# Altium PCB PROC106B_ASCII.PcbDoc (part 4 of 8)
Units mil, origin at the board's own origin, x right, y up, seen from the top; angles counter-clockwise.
Board outline 4498.18 x 1060.53 mil, 8 copper layers (Top Layer, GND1, Sig1, PWR1, PWR2, Sig2, GND2, Bottom Layer), stack 69.602 mil thick; 439 components, 327 nets, 1548 pads, 843 vias.
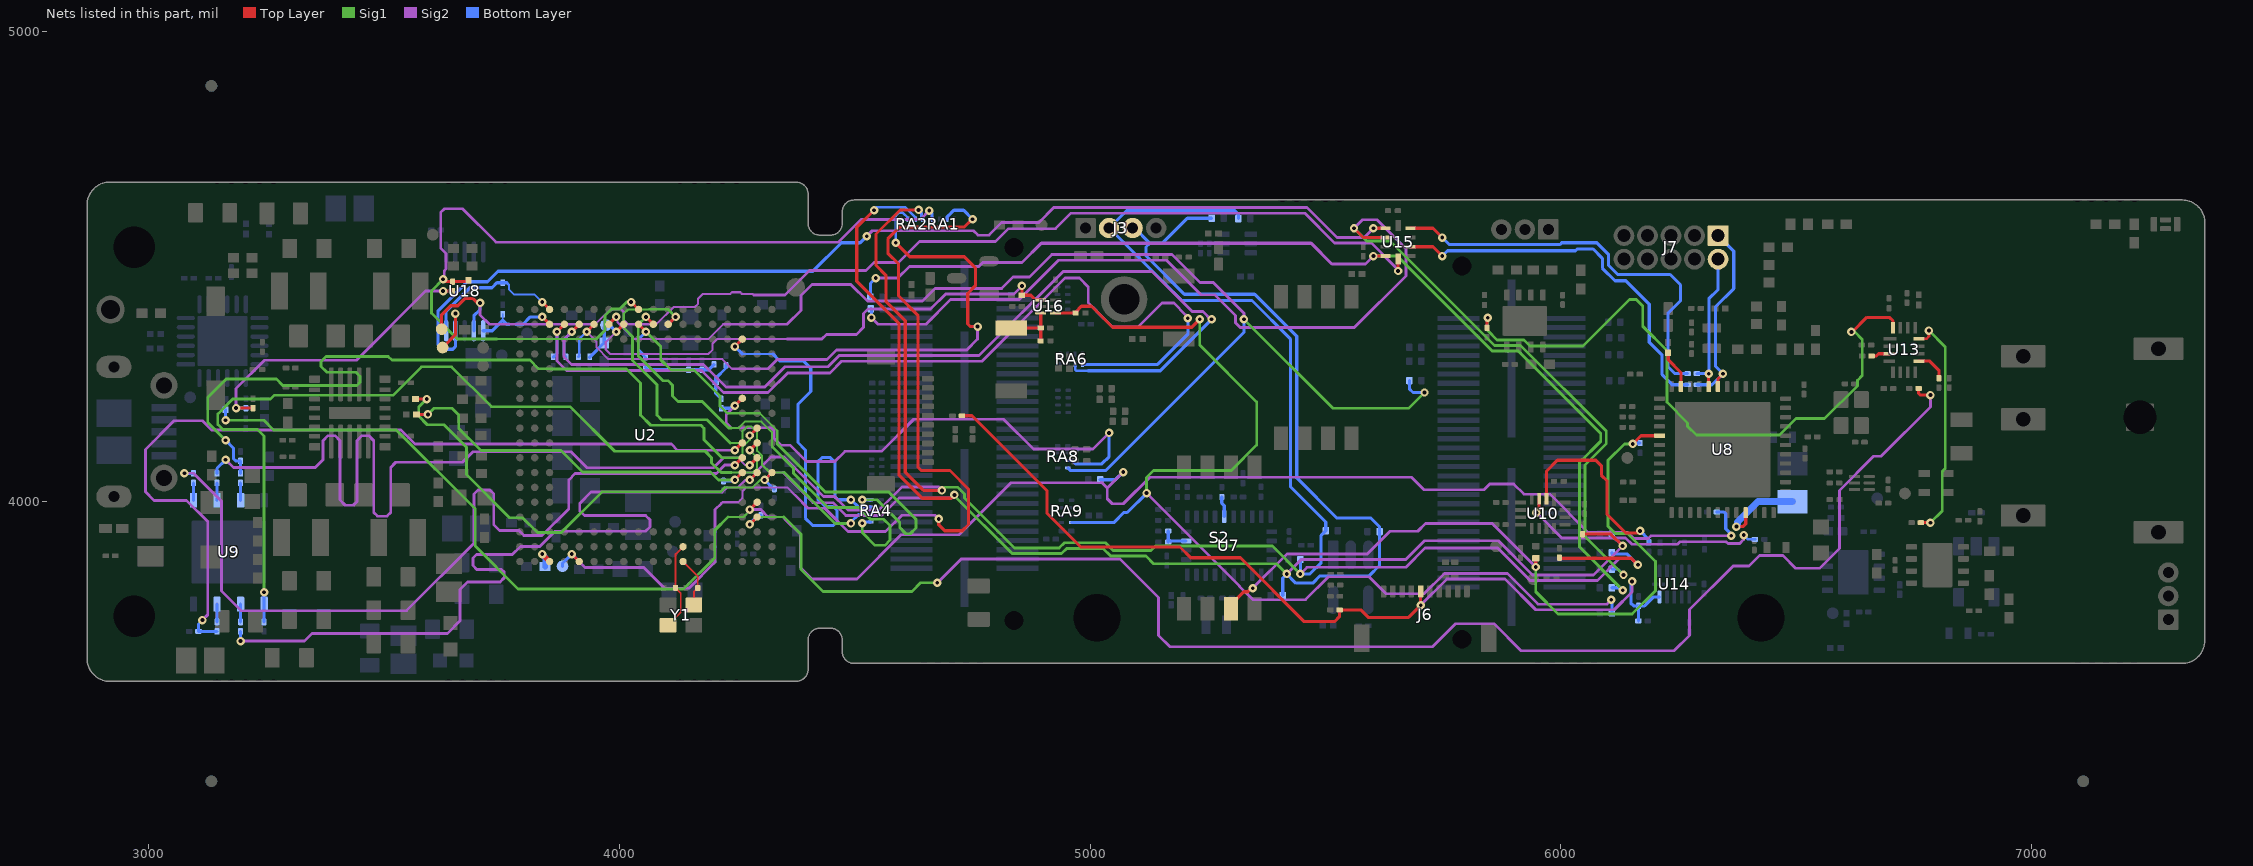
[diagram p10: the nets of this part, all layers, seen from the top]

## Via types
v1: diameter 18, hole 8, Top Layer to Bottom Layer, tented both sides, 804 vias
v2: diameter 19.68, hole 7.87, Top Layer to Bottom Layer, tented both sides, 34 vias
v3: diameter 20, hole 10, Top Layer to Bottom Layer, tented both sides, 3 vias
v4: diameter 18, hole 8, Top Layer to Bottom Layer, 1 vias
v5: diameter 17, hole 7.87, Top Layer to Bottom Layer, 1 vias

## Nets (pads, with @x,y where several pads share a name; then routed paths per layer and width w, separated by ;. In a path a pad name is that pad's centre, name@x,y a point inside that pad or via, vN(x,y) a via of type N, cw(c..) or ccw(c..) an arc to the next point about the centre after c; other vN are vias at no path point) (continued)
AR_MSS_LOGGER: R58.1 R61.1 R131.1 U2.E2 | length 4027.5
  Top Layer w6.7: v1(4276.95,3983.65) U2.E2@4292.7,3999.4
  Sig1 w4.5: 4230.89,3967.9 4263.85,3967.9 v1@4276.95,3981.01
  Sig1 w5.95: v1(3163.55,4173.41) 3244.94,4173.41 3265.5,4152.85 3526.01,4152.85 3694.1,3984.76 3694.1,3905.76 3784.97,3814.9 4136.48,3814.9 4202.76,3881.17 4202.76,3939.76 4230.89,3967.9 ; v1@4276.95,3981.01 v1(4276.95,3983.65)
  Sig2 w4.5: 4332.4,3967.9 4347.49,3967.9 4351.37,3964.02
  Sig2 w5.95: v1(4276.95,3983.65) 4300.25,3983.65 4316,3967.9 4332.4,3967.9 ; 4351.37,3964.02 4384.8,3930.59 4384.8,3860.7 4409.3,3836.2 4504.48,3836.2 4598.64,3930.36 4721.32,3930.36 4831.75,4040.79 5024.98,4040.79 5036.27,4029.5 ; v1(5070.29,4063.51) 5036.27,4029.5 ; v1(6361.81,3928) 6191.21,3928 6185.35,3922.14 6155.37,3922.14 6142.32,3935.19 6057.76,3935.19 5976.45,4016.5 5921.24,4016.5 5899.64,4038.09 5848.9,4038.09 5836.7,4025.89 5709.49,4025.89 5682.87,4052.51 5126.86,4052.51 5070.48,3996.13 5046.92,3996.13 5036.27,4006.77 5036.27,4029.5
  Bottom Layer w6.7: v1(3163.55,4173.41) R61.1@3163.55,4195.73 ; R131.1@6331.18,3978.41 6346.63,3978.41 6350.14,3974.9 6350.14,3942.93 6361.81,3931.25 v1(6361.81,3928)
  Bottom Layer w7: R58.1@5021.79,4046.94 5053.71,4046.94 v1(5070.29,4063.51)
AR_NERR_OUT: R21.1 RA6.5 U2.U15 | length 1993.9
  Top Layer w6.7: v1(3867.5,4361.6) U2.U15@3883.25,4377.35
  Sig2 w5.95: v1(3867.5,4361.6) 3867.5,4299.23 3887.45,4279.28 4174.81,4279.28 4221.6,4232.49 4315.95,4232.49 4357.63,4274.16 4447.2,4274.16 4471.92,4298.87 4770.04,4298.87 4946.76,4475.6 4977.21,4475.6 4995.86,4456.94 4995.86,4423.5 5012.97,4406.38 5012.97,4405.96 5047.64,4371.29 5101.75,4371.29 5152.98,4422.52 5177.86,4422.52 5202.97,4397.42 5202.97,4394.51 v1(5207.55,4389.93)
  Bottom Layer w5.95: R21.1@3859.46,4307.45 3867.5,4315.49 v1(3867.5,4361.6)
  Bottom Layer w6.7: RA6.5@4983.83,4292.08 5143.25,4292.08 5207.55,4356.38 v1(5207.55,4389.93)
AR_NERRIN: R22.1 RA6.6 U2.U14 | length 2037.8
  Top Layer w6.7: v1(3899,4361.6) U2.U14@3914.75,4377.35
  Sig2 w5.95: v1(3899,4361.6) 3882.53,4345.13 3882.53,4307.96 3898.41,4292.07 4178.83,4292.07 4226.53,4244.38 4308.8,4244.38 4351.48,4287.06 4443.29,4287.06 4466.99,4310.77 4763.99,4310.77 4942.88,4489.66 5131.64,4489.66 5216.95,4404.35 5239.74,4404.35 5256.22,4387.88 v1(5258,4387.88)
  Bottom Layer w5: RA6.6@4968.09,4292.08 4968.09,4281.08 4970.49,4278.67 4995.62,4278.67
  Bottom Layer w5.95: R22.1@3886.6,4307.94 R22.1@3886.73,4307.81
  Bottom Layer w6.7: R22.1@3886.73,4308.06 3882.45,4312.34 3882.45,4345.05 v1(3899,4361.6) ; 4995.62,4278.67 5148.79,4278.67 v1(5258,4387.88)
AR_NRST: C130.2 R59.1 R108.1 TP14.1 U2.U11 U16.4 | length 1215.9
  Top Layer w6.7: v1(3993.49,4361.6) U2.U11@4009.24,4377.35 ; v1(4855.01,4458.72) R108.1@4855.01,4439.06 4873.81,4439.06 4883.54,4429.33 U16.4@4894.79,4429.33
  Sig2 w4.5: v1(3993.49,4361.6) 3971.08,4339.19 3971.08,4323.63 3980.36,4314.36 4188.99,4314.36 4198.21,4323.58 4198.21,4336.63 4207.44,4345.85 4210.57,4345.85 4355.81,4345.85
  Sig2 w5.95: 4355.81,4345.85 4429.85,4345.85 4439.71,4355.71 4503.49,4355.71 4518.87,4371.09 4518.87,4400.52 4527.91,4409.56 4661.14,4409.56 4693.34,4441.76 4838.05,4441.76 v1(4855.01,4458.72)
  Bottom Layer w6.7: R59.1@3936.98,4307.45 3967.27,4337.73 C130.2@3967.83,4337.73 3967.83,4371.87 TP14.1@3971.52,4375.57 3979.52,4375.57 v1(3993.49,4361.6)
AR_NRST_1: R177.2 R190.2 RA9.8 U16.1 | length 2330.8
  Top Layer w6.7: U16.1@4926.29,4401.5 R177.2@4969.1,4401.5 4969.1,4403.14 4981.52,4415.55 5002.84,4415.55 5047.49,4370.91 5215.8,4370.91 5232.92,4388.03 v1(5232.92,4387.88)
  Sig1 w5.95: v1(5119.9,4018.83) 5119.9,4051.66 5134.96,4066.71 5299.7,4066.71 5353.73,4120.75 5353.73,4212.26 5232.92,4333.07 v1(5232.92,4387.88)
  Sig2 w5.95: v1(5119.9,4018.83) 5307.53,3831.21 5307.83,3831.21 5317.48,3821.56 5317.48,3820.44 5345.54,3792.38 5457.74,3792.38 5506.4,3841.04 5592.06,3841.04 5628.22,3804.88 5709.46,3804.88 5752.57,3847.99 5886.36,3847.99 5951.51,3782.84 6097.61,3782.84 v1(6107.15,3792.38)
  Bottom Layer w6.7: RA9.8@4960.68,3956.14 5050.1,3956.14 5071.56,3977.6 5078.67,3977.6 v1(5119.9,4018.83) ; v1(6107.15,3792.38) 6108.34,3791.19 R190.2@6108.34,3764.53
AR_NRST_2: C120.1 R124.1 SW2.1 U16.6 | length 121.5
  Top Layer w6.7: SW2.1@4832.84,4369.7 C120.1@4895.16,4369.7 ; R124.1@4894.79,4342.12 4895.16,4342.49 C120.1@4895.16,4369.7 ; U16.6@4895.16,4401.13 C120.1@4895.16,4369.7
AR_OSC_CLKOUT: RA1.3 TP17.1 U2.A14 | length 2160
  Top Layer w6.7: v1(3899,3889.16) U2.A14@3914.75,3873.41 ; v1(4678.32,3963.9) 4678.32,3951.47 4691.07,3938.71 4728.27,3938.71 4741.71,3952.15 4741.71,4027.32 4702.22,4066.81 4641.35,4066.81 4634,4074.16 4634,4396.53 4592.89,4437.64 4592.89,4505.8 4570.34,4528.35 4570.34,4558.71 4570.48,4558.71 4595.75,4583.98 4732.62,4583.98 4749.22,4600.58 v1(4750.21,4600.58)
  Sig2 w4.5: 4216.61,3996.99 4219.01,3999.4 4252.38,3999.4 4260.74,4007.75 4260.74,4008.15 4261.2,4008.62 4261.2,4022.2 4269.9,4030.89 4356.68,4030.89 4374.22,4013.35
  Sig2 w5.95: v1(3899,3889.16) 3927.14,3861.02 4051.83,3861.02 4096.42,3816.43 4147.32,3816.43 4203.16,3872.28 4203.16,3983.55 4216.61,3996.99 ; 4374.22,4013.35 4401.08,3986.49 4436.31,3986.49 4485.8,3937 4565.31,3937 4600.06,3971.75 4670.46,3971.75 v1(4678.32,3963.9)
  Bottom Layer w6.7: TP17.1@3879.25,3863.39 3879.25,3869.41 v1(3899,3889.16) ; RA1.3@4695.96,4600.58 RA1.3@4695.96,4604.84 ; 4699.83,4609.28 4695.96,4605.41 RA1.3@4695.96,4604.84 ; v1(4750.21,4600.58) 4731.24,4619.54 4710.67,4619.54 RA1.3@4695.96,4604.84
AR_PMIC_CLKOUT_SOP2: R85.1 R103.1 RA1.1 U2.V10 | length 1923.4
  Top Layer w6.7: v1@3627.89,4468 R85.1@3645.85,4468 3676.79,4468 R103.1@3679.35,4470.56 ; v1(4024.98,4424.59) U2.V10@4040.73,4408.84
  Sig1 w4.5: 3740,4346 3740.15,4345.85 3950.85,4345.85
  Sig1 w5.95: v1(3625.63,4473) 3600.7,4448.07 3600.7,4400.98 3655.67,4346 3740,4346 ; 3950.85,4345.85 3969.75,4364.75 3969.75,4395.82 3983.5,4409.57 4000.77,4409.57 4015.79,4424.59 v1(4024.98,4424.59)
  Sig2 w5.95: v1(3625.63,4473) 3627.94,4475.31 3627.94,4490.7 3631.71,4494.48 3631.71,4527.96 3620.45,4539.22 3620.45,4614.92 3628.33,4622.8 3666.82,4622.8 3737.83,4551.8 4465.19,4551.8 4513.33,4599.94 4639.35,4599.94 v1(4658.32,4618.91)
  Bottom Layer w6.7: v1(4658.32,4618.91) 4664.47,4612.77 RA1.1@4664.47,4600.58
AR_QSPI_CLK: R47.1 U2.H2 | length 1804.7
  Top Layer w6.7: v1(4276.95,4078.14) U2.H2@4292.7,4093.88
  Sig2 w4.5: 4221.56,4093.88 4251.98,4093.88 4267.73,4078.14 4274.39,4078.14 v1(4276.95,4078.14)
  Sig2 w5.95: v1(3163.55,4089.57) 3180.08,4073.05 3354.04,4073.05 3370.54,4089.54 3370.54,4129.94 3381.32,4140.73 3395.7,4140.73 3406.48,4129.94 3406.48,4004.24 3417.86,3992.86 3434.79,3992.86 3442.43,4000.51 3442.43,4129.94 3453.21,4140.73 3467.59,4140.73 3478.38,4129.94 3478.38,3977.88 3486.54,3969.72 3506.26,3969.72 3514.32,3977.78 3514.32,4034.94 3514.32,4073.37 3525.11,4084.16 3527.46,4084.16 3667.04,4084.16 3689.38,4106.5 3897.64,4106.5 3931.46,4072.68 4200.36,4072.68 4221.56,4093.88
  Bottom Layer w6.7: R47.1@3145.35,4060.46 3145.35,4071.36 v1(3163.55,4089.57)
AR_QSPI_CLK_T: R47.2 U9.6 | length 36.9
  Bottom Layer w6.7: U9.6@3145.35,4003.53 R47.2@3145.35,4040.44
AR_QSPI_CS: R43.1 U2.J2 U9.1 | length 1881.9
  Top Layer w6.7: v1(4276.95,4109.63) U2.J2@4292.7,4125.38
  Sig1 w4.5: 4238.93,4062.39 4283.48,4062.39 4292.7,4071.61 4292.7,4093.88 v1(4276.95,4109.63)
  Sig1 w5.95: v1(3245.35,3808.14) 3245.35,4139.83 3231.35,4153.82 3157.65,4153.82 3147.08,4164.39 3147.08,4186.72 3178.84,4218.48 3258.83,4218.48 3266.76,4226.42 3519.43,4226.42 3579.96,4286.95 3643.5,4286.95 3728.11,4202.33 3895.54,4202.33 3990.27,4107.6 4182.33,4107.6 4195.99,4093.95 4195.99,4082.82 4216.42,4062.39 4237.91,4062.39
  Bottom Layer w6.7: R43.1@3245.35,3744.96 U9.1@3245.35,3783.06 v1(3245.35,3808.14)
AR_QSPI_D0: R6.1 U2.H3 | length 1795.5
  Top Layer w6.7: v1(4245.46,4078.14) U2.H3@4261.2,4093.88
  Sig2 w5.95: v1(3076.13,4060.86) 3095.35,4060.86 3154.78,4001.42 3154.78,3810.48 3196.23,3769.03 3547.84,3769.03 3690.96,3912.15 3690.96,4016.64 3699.5,4025.18 3724.8,4025.18 3733.33,4016.64 3733.33,3951.37 3745.22,3939.48 3786.2,3939.48 3797.13,3928.55 3835.71,3928.55 3892.65,3985.5 3892.65,4046.96 3906.11,4060.42 4206.16,4060.42 4223.87,4078.14 v1(4245.46,4078.14)
  Bottom Layer w6.7: v1(3076.13,4060.86) 3074.85,4062.14 3072.51,4062.14 3074.19,4060.46 R6.1@3095.35,4060.46
AR_QSPI_D0_T: R6.2 U9.5 | length 36.9
  Bottom Layer w6.7: U9.5@3095.35,4003.53 R6.2@3095.35,4040.44
AR_QSPI_D1: R46.1 U2.G2 | length 1770.6
  Top Layer w6.7: v1(4276.95,4046.64) U2.G2@4292.7,4062.39
  Sig2 w4.5: 4228.47,4030.89 4252.08,4030.89 4267.82,4046.64 v1(4276.95,4046.64)
  Sig2 w5.95: v1(3195.35,3704.34) 3330.9,3704.34 3347.26,3720.71 3634.84,3720.71 3661.8,3747.66 3661.8,3814.17 3677.81,3830.18 3746.85,3830.18 3755.52,3838.86 3755.52,3850.5 3749.36,3856.66 3697.09,3856.66 3688.87,3864.88 3688.87,3880.63 3696.63,3888.39 3772.51,3888.39 3789.75,3905.63 3831,3905.63 3863.19,3937.82 4055.69,3937.82 4064.89,3947.02 4064.89,3962.06 4055.92,3971.03 3925.98,3971.03 3915.91,3981.09 3915.91,3996.84 3939.89,4020.82 4218.4,4020.82 4228.47,4030.89
  Bottom Layer w6.7: v1(3195.35,3704.34) R46.1@3195.35,3724.94
AR_QSPI_D1_T: R46.2 U9.2 | length 38.1
  Bottom Layer w6.7: R46.2@3195.35,3744.96 U9.2@3195.35,3783.06
AR_QSPI_D2: R44.1 R48.1 U2.J3 | length 1854.7
  Top Layer w6.7: v1(4245.46,4109.63) U2.J3@4261.2,4125.38
  Sig2 w5.95: v1(3114.34,3749.02) 3125.67,3760.34 3125.67,3958.3 3080.63,4003.33 3011.82,4003.33 2993.41,4021.75 2993.41,4111.63 3054.09,4172.31 3114.23,4172.31 3133.92,4152.62 3536,4152.62 3565.74,4122.88 4110.46,4122.88 4123.7,4109.63 v1(4245.46,4109.63)
  Bottom Layer w6.7: v1(3114.34,3749.02) 3105.99,3740.67 R44.1@3105.99,3724.94 R48.1@3145.35,3724.94
AR_QSPI_D2_T: R48.2 U9.3 | length 38.1
  Bottom Layer w6.7: R48.2@3145.35,3744.96 U9.3@3145.35,3783.06
AR_QSPI_D3: R45.1 R49.1 U2.K2 | length 1774.5
  Top Layer w6.7: v1(4276.95,4141.13) U2.K2@4292.7,4156.88
  Sig1 w4.5: 3828.67,4282.86 3853.37,4282.86 3853.69,4282.54 ; 4236.76,4093.88 4256.22,4093.88 4261.2,4098.87 4261.2,4116.15 4276.95,4131.9 v1(4276.95,4141.13)
  Sig1 w5.95: v1(3163.55,4131.09) 3125.67,4168.98 3125.67,4221.51 3165.01,4260.85 3271.81,4260.85 3285.09,4247.57 3442.38,4247.57 3449.08,4254.28 3449.08,4266.8 3440.5,4275.38 3378.6,4275.38 3366.31,4287.67 3366.31,4298.33 3377.21,4309.23 3508.92,4309.23 3516.76,4301.39 3810.14,4301.39 3810.14,4301.18 3828.57,4282.75 ; 3853.69,4282.54 4014.79,4282.54 4044.76,4252.57 4044.76,4185.79 4045.01,4185.54 4045.01,4184.3 4066.55,4162.76 4173.6,4162.76 4179.99,4156.37 4179.99,4131.98 4218.09,4093.88 4236.76,4093.88
  Bottom Layer w6.7: v1(3163.55,4131.09) 3180.3,4114.35 3180.3,4091.8 3185,4087.09 R45.1@3195.34,4087.09 R49.1@3195.35,4060.46
AR_QSPI_D3_T: R49.2 U9.7 | length 36.9
  Bottom Layer w6.7: U9.7@3195.35,4003.53 R49.2@3195.35,4040.44
AR_RS232RX: R5.2 U2.V16 U18.10 | length 328.8
  Top Layer w6.7: v1(3836.01,4424.59) U2.V16@3851.76,4408.84
  Bottom Layer w4: R5.2@3751.45,4463.67 3762.24,4463.67 3765.83,4460.07 3765.83,4450.94 3775.9,4440.87 3819.73,4440.87 v1(3836.01,4424.59)
  Bottom Layer w6.7: U18.10@3631.98,4363.67 3631.98,4405.07 3681.99,4455.07 3729.37,4455.07 3739.76,4465.47 R5.2@3752.34,4465.47 3760.9,4465.47 3764.48,4461.89
AR_RS232RX_BT: R102.1 U15.4 | length 872.1
  Top Layer w6.7: U15.4@5680.77,4581.32 5728.21,4581.32 v1(5747.9,4561.63)
  Bottom Layer w6.7: v1(5747.9,4561.63) 5762.65,4546.88 5998.24,4546.88 6001.92,4550.56 6076.19,4550.56 6101.44,4525.3 6101.44,4502.14 6120.42,4483.16 6231.98,4483.16 6254.08,4461.06 6254.08,4427.28 6227.56,4400.75 6227.56,4287.33 6242.43,4272.45 R102.1@6268.98,4272.45
AR_RS232TX: R4.2 U2.U16 U18.6 | length 179.6
  Top Layer w6.7: v1(3836.01,4393.1) U2.U16@3851.76,4377.35
  Bottom Layer w4: 3752.37,4386.08 R4.2@3752.37,4398.83 ; 3765.74,4377.35 3780.29,4377.35
  Bottom Layer w6.7: U18.6@3710.72,4363.67 3729.97,4363.67 3752.37,4386.08 3761.1,4377.35 3765.74,4377.35 ; 3780.29,4377.35 3780.48,4377.54 ; 3780.67,4377.35 3795.28,4377.35 3811.02,4393.1 v1(3836.01,4393.1)
AR_RS232TX_BT: R90.1 U15.2 | length 805.8
  Top Layer w6.7: U15.2@5680.77,4541.95 5728.21,4541.95 v1(5747.9,4522.26)
  Bottom Layer w6.7: v1(5747.9,4522.26) 5759.11,4533.48 6030.91,4533.48 6034.59,4537.16 6068.31,4537.16 6088.04,4517.43 6088.04,4496.59 6114.87,4469.76 6138.04,4469.76 6187.61,4420.19 6187.61,4338.81 6215.01,4311.41 6215.01,4270.47 6236.48,4249 R90.1@6268.98,4249
AR_SCL: J3.2 R8.1 R32.1 R51.1 R67.1 R70.2 R99.2 R187.2 RA2.4 U2.G3 | length 5376.7
  Top Layer w6.7: R32.1@3569.24,4185.79 v1(3593.3,4185.79) ; v1(4245.46,4046.64) U2.G3@4261.2,4062.39 ; v1(4635.47,4620.16) 4596.3,4620.16 4545.25,4569.1 4545.25,4502.72 4566.09,4481.87 4566.09,4426.01 4607.2,4384.9 4607.2,4063.06 4645.74,4024.52 v1(4685.21,4024.52) ; R99.2@5996.83,3881.68 5996.83,3880.21 6149.81,3880.21 v1(6163.54,3866.48)
  Sig1 w5.95: v1(3593.3,4185.79) 3606.52,4199 3644.38,4199 3658.97,4184.42 3658.97,4156.03 3706,4109 3876,4109 3921.47,4063.53 4193.8,4063.53 4210.69,4046.64 v1(4245.46,4046.64) ; v1(4685.21,4024.52) 4692.07,4031.37 4718.53,4031.37 4733.17,4016.73 4733.17,4008.22 4839.36,3902.03 4934.23,3902.03 4945.47,3913.27 5032.3,3913.27 5048.61,3896.95 5129.55,3896.95 5138.86,3906.27 5387.15,3906.27 v1(5446.44,3846.98)
  Sig2 w4.5: v1(4245.46,4046.64) 4261.2,4062.39 4284.5,4062.39
  Sig2 w5.95: 4284.5,4062.39 4289.36,4062.39 4322.44,4095.46 4349.94,4095.46 4433.87,4011.54 4457.3,4011.54 4486,3982.83 4551.88,3982.83 4600.46,4031.41 4678.31,4031.41 v1(4685.21,4024.52) ; v1(5446.44,3846.98) 5460.56,3861.09 5670.52,3861.09 5711.63,3902.2 5865.8,3902.2 5934.83,3833.17 6077.4,3833.17 6123.79,3879.56 6149.05,3879.56 6162.13,3866.48 v1(6163.54,3866.48)
  Bottom Layer w6.7: R8.1@4221.23,4044.42 4243.24,4044.42 v1(4245.46,4046.64) ; v1(4635.47,4620.16) 4641.72,4613.9 4641.72,4603.34 RA2.4@4644.48,4600.58 ; R51.1@5314.8,4601.84 5314.8,4611.25 5307.13,4618.93 5077.46,4618.93 J3.2@5040.29,4581.75 5194.28,4427.76 5343.89,4427.76 5425.37,4346.28 5425.37,4032.66 5500.54,3957.49 R67.1@5500.54,3938.91 5490.54,3928.91 5490.54,3870.63 5466.89,3846.98 v1@5446.8,3846.98 ; v1(5446.44,3846.98) v1@5446.8,3846.98 ; R70.2@5446.8,3877.69 v1@5446.8,3846.98 ; R187.2@6108.34,3892.26 6108.34,3889.24 6140.78,3889.24 v1(6163.54,3866.48)
AR_SDA: J3.3 R7.1 R28.1 R57.1 R68.1 R71.2 R101.2 R186.2 RA2.3 U2.G1 | length 5570.2
  Top Layer w6.7: R28.1@3566.89,4218.48 v1(3590.95,4218.48) ; v1(4308.45,4046.64) U2.G1@4324.2,4062.39 ; v1(4541.01,4619.79) 4504.36,4583.14 4504.36,4468.8 4593.8,4379.35 4593.8,4057.51 4643.39,4007.92 4704.73,4007.92 v1(4711.71,4014.9) ; R101.2@6046.19,3931.55 6106.05,3931.55 v1(6131.02,3906.59)
  Sig1 w4.5: 4223.95,4030.89 4283.48,4030.89 4299.22,4046.64 v1(4308.45,4046.64)
  Sig1 w5.95: v1(3590.95,4218.48) 3573.79,4201.33 3573.79,4182.21 3592,4164 3627.18,4164 3675,4116.18 3675,4058 3766.5,3966.5 3794.5,3966.5 3826,3935 3876.7,3935 3963.12,4021.42 4214.48,4021.42 4223.95,4030.89 ; v1(4711.71,4014.9) 4711.71,4012.86 4834.43,3890.14 4939.16,3890.14 4950.39,3901.38 5027.37,3901.38 5043.69,3885.06 5118.56,3885.06 5134.9,3868.71 5395.87,3868.71 v1(5417.61,3846.98)
  Sig2 w4.5: v1(4308.45,4046.64) 4324.2,4062.39 4347.49,4062.39
  Sig2 w5.95: 4347.49,4062.39 4411.45,3998.42 4453.59,3998.42 4481.08,3970.94 4556.8,3970.94 4593.91,4008.04 4704.85,4008.04 v1(4711.71,4014.9) ; v1(5417.61,3846.98) 5448.43,3877.79 5670.4,3877.79 5710.25,3917.64 5867.17,3917.64 5939.75,3845.06 6069.49,3845.06 v1(6131.02,3906.59)
  Bottom Layer w5: v1(4541.01,4619.79) 4546.89,4625.68 4607.49,4625.68 4628.74,4604.43 RA2.3@4628.74,4600.58
  Bottom Layer w6.7: v1(4308.45,4046.64) 4327.65,4027.44 R7.1@4329.25,4027.44 ; J3.3@5090.29,4581.75 5095.03,4581.75 5127.03,4549.75 ; R57.1@5258,4602.69 5206.48,4602.69 5153.54,4549.75 5127.03,4549.75 ; R71.2@5409.05,3801.26 5409.05,3838.42 v1(5417.61,3846.98) 5436.94,3827.64 5472.95,3827.64 5488.3,3842.99 5592.79,3842.99 5614.67,3864.87 R68.1@5614.67,3937.06 5614.67,3947.67 5596.41,3965.94 5523.8,3965.94 5438.77,4050.97 5438.77,4351.83 5349.44,4441.16 5200.24,4441.16 5118.68,4522.72 5118.68,4541.4 5127.03,4549.75 ; R186.2@6108.34,3931.22 6108.34,3929.27 v1(6131.02,3906.59)
AR_SOP0: R83.2 R158.2 R159.1 R174.2 | length 153.2
  Bottom Layer w6.7: R83.2@4055.26,4286.87 4061.4,4280.73 R174.2@4147.23,4280.73 R158.2@4175.56,4280.73 4189.83,4280.73 R159.1@4201.23,4292.13
AR_SOP1: R84.2 R170.2 R171.1 | length 85.3
  Bottom Layer w6.7: R84.2@4216.3,4218.86 4204.73,4230.43 R170.2@4204.73,4253.13 4204.73,4262.79 4226.45,4284.51 R171.1@4226.45,4290.4
AR_SOP2: R85.2 R172.2 R176.2 | length 643.8
  Top Layer w6.7: v1(3185.9,4199.43) R176.2@3221.71,4199.43 ; v1(3625.63,4447.98) R85.2@3645.85,4447.98
  Sig2 w5.95: v1(3185.9,4199.43) 3185.9,4240.85 3246.04,4301 3441.34,4301 3588.32,4447.98 v1(3625.63,4447.98)
  Bottom Layer w6.7: v1(3185.9,4199.43) R172.2@3206.71,4199.43
AR_SPICLK1: R75.2 R136.2 U2.D2 | length 3279.1
  Top Layer w6.7: v1(4276.95,3952.15) U2.D2@4292.7,3967.9 ; R136.2@6759.84,4241 6759.84,4230.98 6763.81,4227 v1(6784.81,4227)
  Sig1 w4.5: v1(4276.95,3952.15) 4292.7,3967.9 4349.27,3967.9 4349.34,3967.83
  Sig1 w5.95: 4349.34,3967.83 4385.89,3931.28 4385.89,3856.5 4432.49,3809.9 4621.29,3809.9 4639.82,3828.43 v1(4675.5,3828.43)
  Sig2 w5.95: v1(4675.5,3828.43) 4726.11,3879.04 5063.11,3879.04 5145.43,3796.73 5145.43,3716.52 5169.69,3692.25 5727.49,3692.25 5776.66,3741.42 5857.96,3741.42 5915.5,3683.88 6240.37,3683.88 6273.14,3716.64 6273.14,3771.13 6365.96,3863.95 6399.47,3863.95 6421.81,3886.29 6471.49,3886.29 6498.84,3858.94 6549.45,3858.94 6591.81,3901.3 6591.81,4024.46 6664.35,4097 6679.86,4097 6784.81,4201.95 v1(6784.81,4227)
  Bottom Layer w5: v1@4276.95,3954.07 v1@4278.87,3954.07
  Bottom Layer w6.7: v1@4276.95,3954.07 4289.54,3966.66 4295.76,3966.66 R75.2@4300.76,3971.66
AR_SYNC_IN: R157.1 RA8.8 U2.U12 | length 2620.6
  Top Layer w6.7: U2.U12@3977.74,4377.35 v1(3993.49,4393.1)
  Sig1 w5.95: v1(5326.65,4387.88) 5515.35,4199.18 5676.96,4199.18 v1(5710.24,4232.45)
  Sig2 w4.5: v1(3993.49,4393.1) 3996.07,4390.51 3996.07,4381.95 4032.17,4345.85 4063,4345.85 4112.95,4345.85 4188.99,4345.85 4220.48,4377.35 4356.34,4377.35
  Sig2 w5.95: 4356.34,4377.35 4385.89,4406.89 4385.89,4438.68 4409.3,4462.1 4491.39,4462.1 4526.87,4426.61 4643.58,4426.61 4670.63,4453.66 4812.05,4453.66 4836.34,4477.95 4871.22,4477.95 4918.61,4525.34 5174.08,4525.34 5233.52,4465.91 5261.55,4465.91 5326.65,4400.81 v1(5326.65,4387.88)
  Bottom Layer w6.7: RA8.8@4952.69,4072.25 4957.85,4067.09 5033.79,4067.09 5326.65,4359.96 v1(5326.65,4387.88) ; R157.1@5678.13,4257.72 5678.13,4240.18 5685.85,4232.45 v1(5710.24,4232.45)
AR_SYNC_OUT_SOP1: R84.1 RA8.7 U2.M3 | length 1179
  Top Layer w6.7: v1(4245.46,4204.12) U2.M3@4261.2,4219.87
  Sig2 w4.5: 4235.73,4159.06 4237.91,4156.88 4253,4156.88
  Sig2 w5.95: 4235.73,4159.06 4227.18,4167.6 4227.18,4185.84 v1(4245.46,4204.12) ; 4253.73,4157.6 4322.82,4157.6 4329.06,4151.36 4329.06,4134.78 4343.24,4120.6 4362.86,4120.6 4397.76,4085.71 4457.46,4085.71 4479.23,4107.47 4557.18,4107.47 4625.34,4175.63 4816.08,4175.63 4879.55,4112.15 5005.9,4112.15 v1(5040.24,4146.48)
  Bottom Layer w6.7: R84.1@4216.3,4198.83 4240.17,4198.83 v1(4245.46,4204.12) ; RA8.7@4952.69,4088 4961.76,4088 4968.99,4080.76 5024.83,4080.76 5040.29,4096.22 5040.29,4135.89 5040.24,4135.94 v1(5040.24,4146.48)
AR_TCK: RA4.3 U2.T3 | length 974.4
  Top Layer w6.7: v1(4245.46,4330.1) U2.T3@4261.2,4345.85
  Bottom Layer w5: 4261.2,4314.36 4325.67,4314.36
  Bottom Layer w6.7: v1(4245.46,4330.1) 4261.2,4314.36 ; 4325.67,4314.36 4340.28,4299.75 4390.87,4299.75 4406.51,4284.11 4406.51,4234.46 4379.38,4207.33 4379.38,4126.23 4395.25,4110.36 4395.25,3965.55 4410.79,3950.01 4454.85,3950.01 4462.29,3957.46 4462.29,3981.86 4453.83,3990.33 4436.99,3990.33 4421.62,4005.71 4421.62,4085.22 4430.48,4094.08 4448.07,4094.08 4457.75,4084.4 4457.75,4011.34 4464.36,4004.73 v1(4491.92,4004.73) ; v1@4492.09,4004.91 4510.56,3986.44 4523.94,3986.44 4526.49,3988.99 RA4.3@4534.27,3988.99
AR_TDI: RA4.1 U2.U9 | length 989.4
  Top Layer w6.7: v1(4056.48,4393.1) U2.U9@4072.23,4377.35
  Sig1 w4.5: 4237.91,4156.88 4253.05,4156.88 4266.69,4170.51 4301.34,4170.51 4323.86,4147.99 ; 4324.2,4147.65 4324.2,4117.62 4324.92,4116.89
  Sig1 w5.95: v1(4056.48,4393.1) 4040.01,4376.62 4040.01,4309.82 4092.23,4257.6 4103.3,4257.6 4112.95,4247.95 4112.95,4224.77 4124.62,4213.1 4176.21,4213.1 4232.44,4156.88 4237.91,4156.88 ; 4324.92,4116.89 4370.19,4071.63 4370.19,4060.96 4442.99,3988.16 4508.96,3988.16 4534.07,3963.06 4561.59,3963.06 4575.01,3949.63 4575.01,3918.91 4563.91,3907.8 4543.12,3907.8 4516.02,3934.9 v1(4516.02,3954.47)
  Bottom Layer w6.7: v1(4516.02,3954.47) 4519.04,3957.49 RA4.1@4534.27,3957.49
AR_TDO_SOP0: R83.1 RA4.4 U2.U10 | length 1066.3
  Top Layer w6.7: U2.U10@4040.73,4377.35 v1(4056.48,4361.6)
  Sig1 w4.5: 4226.28,4191.13 4229.04,4188.37 4298.25,4188.37 4335.37,4151.25 4335.37,4123.27
  Sig1 w5.95: v1(4056.48,4361.6) 4087.98,4330.1 4087.98,4302.05 4109.96,4280.07 4158.63,4280.07 4213.96,4224.74 4213.96,4203.45 4226.28,4191.13 ; 4335.37,4123.27 4437.43,4021.21 4572.32,4021.21 4630.43,3963.1 4630.43,3944.98 4617.97,3932.52 4608.42,3932.52 4595.57,3945.37 4595.57,3956.09 4546.92,4004.73 v1(4516.02,4004.73)
  Bottom Layer w5.95: R83.1@4055.26,4306.9 4047.92,4314.24 4047.92,4315.79 4040.31,4323.4 4040.31,4345.43 v1(4056.48,4361.6)
  Bottom Layer w6.7: v1(4516.02,4004.73) RA4.4@4534.27,4004.74
AR_TMS: RA4.2 U2.U8 | length 1020.5
  Top Layer w6.7: U2.U8@4103.72,4377.35 v1(4119.47,4393.1)
  Sig1 w4.5: 4012.76,4366.34 4009.24,4369.87 4009.24,4399.62 4018.46,4408.84 4063.71,4408.84 ; 4235.58,4125.38 4255.66,4125.38 4261.2,4130.93 4261.2,4150.25 4271.01,4160.06 4280.29,4160.06 4292.7,4147.65 4292.7,4134.6 4292.7,4108.66 4303.15,4098.21 4303.15,4079.13 4319.89,4062.39 4350.27,4062.39
  Sig1 w5.5: 4063.71,4408.84 4103.72,4408.84
  Sig1 w5.95: 4012.76,4366.34 4028.11,4350.99 4028.11,4300.71 4080.01,4248.82 4080.01,4184.3 4089.66,4174.66 4186.31,4174.66 4235.58,4125.38 ; 4103.72,4408.84 v1(4119.47,4393.1) ; 4350.27,4062.39 4458.22,3954.44 v1(4491.92,3954.44)
  Bottom Layer w6.7: v1(4491.92,3954.44) 4491.92,3957.3 4507.67,3973.04 4529.49,3973.04 4529.69,3973.24 RA4.2@4534.27,3973.24
AR_VBGAP: C69.1 U2.A16 | length 51.5
  Top Layer w12: v1(3836.01,3889.16) U2.A16@3851.76,3873.41
  Bottom Layer w12: v1(3836.01,3889.16) 3842.44,3882.73 C69.1@3842.44,3862.61
AR_WARMRST: R23.1 RA2.2 U2.U13 | length 1439.2
  Top Layer w6.7: v1(3930.5,4361.6) U2.U13@3946.24,4377.35 ; v1(4586.89,4550.32) 4616.57,4520.65 4732.64,4520.65 4756.13,4497.15 4756.13,4458.87 4739.91,4442.64 4739.91,4377.98 4745.37,4372.52 v1(4761,4372.52)
  Sig2 w4.5: v1(3930.5,4361.6) 3951.62,4340.47 3951.62,4328.31 3976.69,4303.25 4218.55,4303.25 4238.93,4282.86 4314.97,4282.86
  Sig2 w5.95: 4315.78,4282.86 4335.38,4302.46 4440.95,4302.46 4461.15,4322.66 4737.94,4322.66 4761,4345.72 v1(4761,4372.52)
  Bottom Layer w5: R23.1@3913.05,4308.06 3914.7,4309.71 3914.7,4345.8 v1(3930.5,4361.6) ; v1(4586.89,4550.32) 4586.89,4607.62 4593.25,4613.98 4602.64,4613.98 4612.99,4603.63 RA2.2@4612.99,4600.58
AR_XTAL_N: C71.1 U2.B7 Y1.3 | length 189.4
  Top Layer w4: Y1.3@4103.21,3737.98 4130.48,3765.26 4130.48,3806.44 C71.1@4119.48,3817.45 4119.35,3817.58 4119.35,3889.03 U2.B7@4135.22,3904.91
AR_XTAL_P: C14.1 U2.A7 Y1.1 | length 112.5
  Top Layer w4: U2.A7@4135.22,3873.41 4166.48,3842.15 C14.1@4166.48,3817.27 4158.32,3809.11 Y1.1@4158.32,3777.29
BOOTN: R80.2 R96.1 U7.4 | length 61.7
  Bottom Layer w6.7: R96.1@5166,3938 R80.2@5166,3915 5168.06,3917.06 U7.4@5203.84,3917.06
BREAK_RS232RX: TP19.1 U15.6 U18.9 | length 2414.4
  Top Layer w6.7: TP19.1@3624.53,4327.96 3651.67,4355.1 v1(3651.67,4400.1) ; v1(5601.8,4581.32) U15.6@5627.62,4581.32
  Sig2 w5.95: v1(4525.62,4564.56) 4537.22,4576.15 4752.1,4576.15 4761.6,4566.65 4784.9,4566.65 4811.82,4593.56 4891.05,4593.56 4922.76,4625.27 5460.93,4625.27 5524.35,4561.85 5582.34,4561.85 v1(5601.8,4581.32)
  Bottom Layer w6.7: v1(3651.67,4400.1) U18.9@3651.67,4363.67 3651.67,4329.8 3646.2,4324.34 3625.03,4324.34 3614.44,4334.93 3614.44,4405.27 3676.79,4467.62 3719.88,4467.62 3742.11,4489.85 4411.03,4489.85 4471.76,4550.57 4511.53,4550.57 4525.51,4564.56 v1(4525.62,4564.56)
BREAK_RS232TX: TP18.1 U15.10 U18.7 | length 2404.6
  Top Layer w6.7: TP18.1@3622.56,4367.08 3622.56,4397.71 3641.55,4416.7 3656.78,4416.7 3672.52,4432.45 3688.23,4432.45 3701.04,4419.64 3704.07,4422.68 v1(3704.17,4422.68) ; v1(5654.19,4490.55) U15.10@5654.19,4516.36
  Sig2 w4.5: 3757.52,4377.35 3949.08,4377.35 3980.57,4408.84 4003.69,4408.84 4009.24,4403.3 4009.24,4386.57 4018.46,4377.35 4078.74,4377.35 4115.31,4413.92 4160.41,4413.92 4166.72,4420.23 4166.72,4431.11 4177.13,4441.52 4235.22,4441.52 4238.98,4445.28 4256.76,4445.28 4260.52,4441.52 4283.32,4441.52 4285.43,4439.41
  Sig2 w5.95: v1(3704.17,4422.68) 3704.17,4396.97 3723.79,4377.35 3757.52,4377.35 ; 4285.43,4439.41 4351.66,4439.41 4404.06,4491.81 4523.81,4491.81 4540.78,4508.77 4593.31,4508.77 4637.45,4552.91 4798.86,4552.91 4826.36,4580.42 4926.72,4580.42 4959.68,4613.38 5456.01,4613.38 5519.43,4549.96 5597.4,4549.96 5654.19,4493.17 v1(5654.19,4490.55)
  Bottom Layer w6.7: U18.7@3691.04,4363.67 3691.04,4395.72 3704.17,4408.85 v1(3704.17,4422.68)
"BT ENABLE": R30.1 R110.1 S2.3 U8.17 | length 1611.9
  Top Layer w6.7: S2.3@5299.37,3773.46 5299.37,3781.83 5326.65,3809.11 5335.01,3809.11 5342.67,3816.77 v1(5345.19,3816.77) ; v1(6152.53,4123.13) 6170.03,4140.64 U8.17@6209.52,4140.64
  Top Layer w7: v1(5946.67,3861.76) R30.1@5946.67,3880.72
  Sig1 w5.95: v1(5946.67,3861.76) 5946.67,3809.24 5993.83,3762.08 6151.35,3762.08 6200.62,3811.35 6200.62,3873.79 6141.21,3933.2 6115.53,3933.2 6100.29,3948.44 6100.29,4088.49 6134.93,4123.13 v1(6152.53,4123.13)
  Sig2 w5.95: v1(5345.19,3816.77) 5418.11,3889.69 5588.66,3889.69 5636.7,3937.73 5695.79,3937.73 5712.26,3954.2 5854.23,3954.2 v1(5946.67,3861.76)
  Bottom Layer w6.7: v1(6152.53,4123.13) 6154.66,4125.26 R110.1@6168.27,4125.26
BT_RST: R91.2 U10.3 | length 549.1
  Top Layer w6.7: v1(5947.91,3977.25) 5953.68,3983.02 U10.3@5953.68,4006.69 ; v1(6388.18,3929.64) v1@6391.36,3926.46
  Sig2 w5.95: v1(5947.91,3977.25) 6001.87,3923.29 6137.4,3923.29 6150.44,3910.25 6248.08,3910.25 6253.35,3915.52 6351,3915.52 6354.99,3911.53 6379.77,3911.53 6388.18,3919.94 v1(6388.18,3929.64)
  Bottom Layer w5.95: v1(6388.18,3929.64) 6397.29,3920.53 R91.2@6412.14,3920.53
BT_UART_RX: J7.1 R90.2 U8.7 | length 426
  Top Layer w6.7: U8.7@6333.54,4244.97 6333.58,4245 6333.58,4261.53 v1(6344.18,4272.14)
  Bottom Layer w5.5: J7.1@6333.84,4565.56 J7.1@6340.47,4558.92
  Bottom Layer w6.7: R90.2@6289,4249 6321.04,4249 v1(6344.18,4272.14) 6328.44,4287.88 6328.44,4414.44 6367,4453 6367,4532.4 J7.1@6340.47,4558.92
BT_UART_TX: J7.2 R102.2 U8.8 | length 303.9
  Top Layer w6.7: U8.8@6313.85,4244.97 v1(6313.85,4272.45)
  Bottom Layer w6.7: R102.2@6289,4272.45 v1(6313.85,4272.45) 6314.6,4273.2 6314.6,4431.5 6314.33,4431.77 6333.84,4451.28 J7.2@6333.84,4515.56
CAN1_FD_RX: R127.2 U13.3 | length 39.7
  Top Layer w6.7: R127.2@6659.81,4310 6669.93,4310 6674.81,4314.88 U13.3@6697.44,4314.88
CAN1_FD_TX: R123.2 U13.16 | length 1396.9
  Top Layer w5.5: v1@5843.14,4390.03 v1(5844.47,4391.36)
  Top Layer w6.7: R123.2@5843.14,4369.72 v1@5843.14,4390.03 ; v1(6617,4361) 6619,4361 6650,4392 6697.81,4392 6705.32,4384.5 U13.16@6705.32,4370
  Sig1 w5.95: v1(5844.47,4391.36) 5844.47,4364.44 5864.63,4344.28 5921.27,4344.28 5934.47,4331.08 6047.05,4331.08 6145.89,4429.93 6160.16,4429.93 6173.93,4416.16 6173.93,4399.44 6173.8,4399.32 6173.8,4373.16 6225.17,4321.8 6225.17,4211.88 6269.16,4167.89 6269.16,4160.84 6288.11,4141.89 6464.32,4141.89 6499.36,4176.94 6560.03,4176.94 6629.71,4246.61 6629.71,4258.29 6639.96,4268.53 6639.96,4345.36 6624.31,4361 v1(6617,4361)
CAN2_FD_RX: R120.2 U13.9 | length 67.4
  Top Layer w6.7: U13.9@6760.43,4299.13 6783.77,4299.13 6802.81,4280.09 R120.2@6802.81,4263
CAN2_FD_TX: R116.2 U13.12 | length 490.9
  Top Layer w5.5: U13.12@6760.43,4346.38 6776.09,4346.38 6781.81,4352.1 v1(6781.81,4364)
  Top Layer w6.7: R116.2@6764.81,3956 v1(6784.78,3956)
  Sig1 w5.95: v1(6781.81,4364) 6816.25,4329.56 6816.25,4071.26 6809.9,4064.92 6809.9,3981.12 v1(6784.78,3956)
CLKSEL0: R82.2 U7.10 | length 43.9
  Bottom Layer w6.7: R82.2@5279.72,4010.48 5279.72,3997.37 5285.04,3992.06 U7.10@5285.04,3968.74
CONN_AR_RS232RX: R14.2 R188.2 U15.7 | length 2708.7
  Top Layer w6.7: v1(5560.49,4581.32) 5580.17,4561.63 U15.7@5627.62,4561.63
  Sig1 w5.95: v1(5560.49,4581.32) 5587.65,4554.15 5637.36,4554.15 5859.12,4332.39 5914.31,4332.39 6096.46,4150.24 6096.46,4124 6051.11,4078.65 6051.11,3926.7 v1(6132.95,3844.86)
  Sig2 w5.95: v1(4535.35,4391.71) 4549.64,4377.41 4651.24,4377.41 4703.69,4429.87 4849.45,4429.87 4933.03,4513.45 5161.86,4513.45 5235.02,4440.28 5263.83,4440.28 5308.48,4395.63 5308.48,4381.06 5308.34,4380.92 5318.8,4370.45 5561.15,4370.45 5670.66,4479.97 5670.66,4537.85 5609.13,4599.39 5578.55,4599.39 v1(5560.49,4581.32)
  Bottom Layer w6.7: R14.2@4534.32,4410.25 4535.35,4409.22 v1(4535.35,4391.71) ; R188.2@6108.34,3857.41 6120.4,3857.41 v1(6132.95,3844.86)
CONN_AR_RS232TX: R12.2 R189.2 U15.9 | length 2238.4
  Top Layer w6.7: v1(5601.8,4522.26) U15.9@5627.62,4522.26
  Sig1 w5.95: v1(5601.8,4522.26) 5652.42,4522.26 5854.19,4320.49 5909.38,4320.49 6084.56,4145.31 6084.56,4128.92 6039.22,4083.58 6039.22,3904.68 v1(6131.43,3812.47)
  Sig2 w6.7: v1(4544.64,4475.55) 4591.67,4475.55 4616.2,4500.09 4763.38,4500.09 4771.85,4508.55 4855.38,4508.55 4896.34,4549.51 5469.51,4549.51 5513.6,4505.42 5584.95,4505.42 v1(5601.8,4522.26)
  Bottom Layer w6.7: R12.2@4533.36,4434.59 4533.36,4464.27 v1(4544.64,4475.55) ; R189.2@6108.34,3817.56 6126.34,3817.56 v1(6131.43,3812.47)
DCDC_SW: L7.1 U8.33 | length 190.7
  Top Layer w6.7: v1(6372.8,3947.63) 6386.54,3947.63 6392.59,3953.68 U8.33@6392.59,3977.25
  Bottom Layer w15: v1@6374.8,3947.63 6374.8,3957.22 6418.41,4000.83 L7.1@6491.96,4000.83
DIO6_GLED: R17.1 U8.11 | length 82.8
  Top Layer w6.7: R17.1@6227.85,4316.62 6227.85,4301.96 6254.8,4275.01 U8.11@6254.8,4244.97
DISP: R168.2 U10.2 | length 417.7
  Top Layer w6.7: U10.2@5969.43,4006.69 5969.43,4065.41 5992.45,4088.43 6074.39,4088.43 6086.01,4076.82 6086.01,4057.02 6098,4045.03 6098,3973.98 6137.85,3934.13 6163.85,3934.13 v1(6168.18,3938.46)
  Bottom Layer w6.7: v1(6168.18,3938.46) 6186.75,3919.9 R168.2@6186.75,3914.4
DISP_T: C114.2 J6.5 R180.2 R181.1 R182.1 U14.5 | length 1935.7
  Top Layer w6.7: R182.1@4727.72,4183.18 4749.07,4183.18 4908.34,4023.9 4908.34,3975.92 4980.06,3904.2 5190.94,3904.2 5213.79,3881.35 5319.43,3881.35 5454.98,3745.8 5519.01,3745.8 5530.06,3756.85 R181.1@5530.06,3770.65 5574.92,3770.65 5590.72,3754.84 5676.41,3754.84 v1(5702.06,3780.5) J6.5@5702.06,3810.06
  Sig2 w5.95: v1(5702.06,3780.5) 5757.66,3836.09 5881.44,3836.09 5946.59,3770.95 6113.2,3770.95 6151.04,3808.79 v1(6151.04,3831.01)
  Bottom Layer w6.7: v1(6151.04,3831.01) 6148.69,3828.66 6148.69,3784.92 6154.47,3779.14 R180.2@6165.19,3779.14 ; C114.2@6164.56,3747.34 6164.56,3778.51 R180.2@6165.19,3779.14 ; U14.5@6209.55,3797.8 6196.48,3797.8 6177.82,3779.14 R180.2@6165.19,3779.14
